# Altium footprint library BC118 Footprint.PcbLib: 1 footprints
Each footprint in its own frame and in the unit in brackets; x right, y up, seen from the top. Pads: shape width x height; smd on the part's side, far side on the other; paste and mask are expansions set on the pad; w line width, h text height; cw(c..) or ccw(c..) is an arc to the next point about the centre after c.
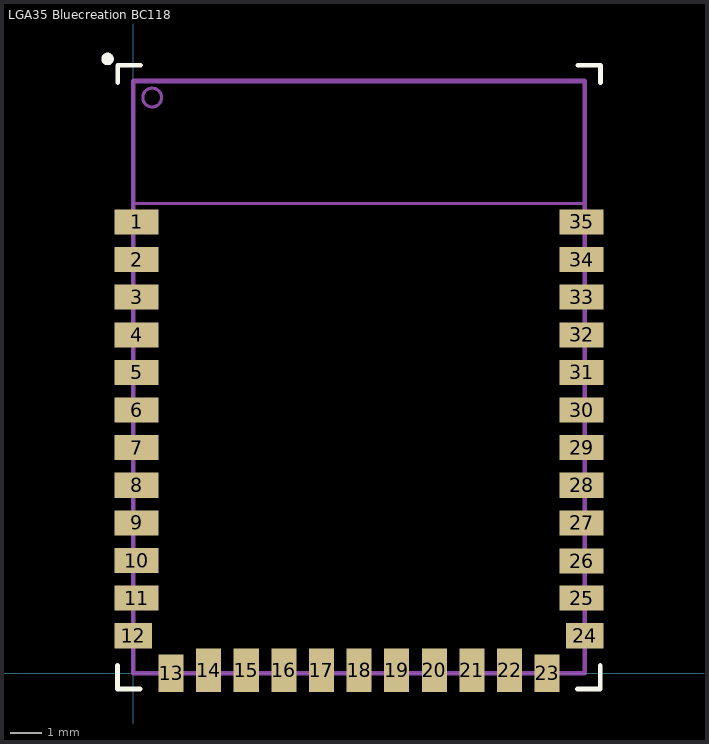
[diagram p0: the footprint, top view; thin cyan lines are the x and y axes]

## LGA35 Bluecreation BC118 [mm] "LGA, 35Leads, Body 14.4x18.9mm, Pitch 1.2mm"
height 2.5
pads (35):
  rect 1.4x0.8 smd paste+0: 1(0.1,14.4) 2(0.1,13.2) 3(0.1,12) 4(0.1,10.8) 5(0.1,9.6) 6(0.1,8.4) 7(0.1,7.2) 8(0.1,6) 9(0.1,4.8) 10(0.1,3.6) 11(0.1,2.4) 25(14.3,2.4) 26(14.3,3.58) 30(14.3,8.4) 31(14.3,9.6) 32(14.3,10.8) 33(14.3,12) 34(14.3,13.2) 35(14.3,14.4)
  rect 1.2x0.8 smd paste+0: 12(0,1.2) 24(14.4,1.2)
  rect 0.8x1.2 smd paste+0: 13(1.2,0) 23(13.2,0)
  rect 0.8x1.4 smd paste+0: 14(2.4,0.1) 15(3.6,0.1) 16(4.8,0.1) 17(6,0.1) 18(7.2,0.1) 19(8.4,0.1) 20(9.6,0.1) 21(10.8,0.1) 22(12,0.1)
  rect 1.4x0.8 smd: 27(14.3,4.8) 28(14.3,6) 29(14.3,7.2)
Top Overlay:
  circle w0.2: c-0.825,19.6 r0.1
  lines w0.15: -0.51,0.25 -0.51,-0.5 0.215,-0.5 ; -0.5,18.85 -0.5,19.4 0.225,19.4 ; 14.17,-0.5 14.895,-0.5 14.895,0.25 ; 14.175,19.4 14.9,19.4 14.9,18.85
Mechanical 4:
  circle w0.1: c0.6,18.37 r0.3
  lines w0.1: 0,14.99 14.4,14.99
  lines w0.15: 0,0 0,18.9 14.4,18.9 14.4,0 0,0
  text ".Designator" at 7.2,9.45 h0.6
  text "GND Cut Out" at 3.28,16.31 h0.8
3D body: height 2.5, standoff 0, extent 0,0 14.4,14.99
3D body: height 1.32, standoff 0, extent 0,14.99 14.4,18.9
